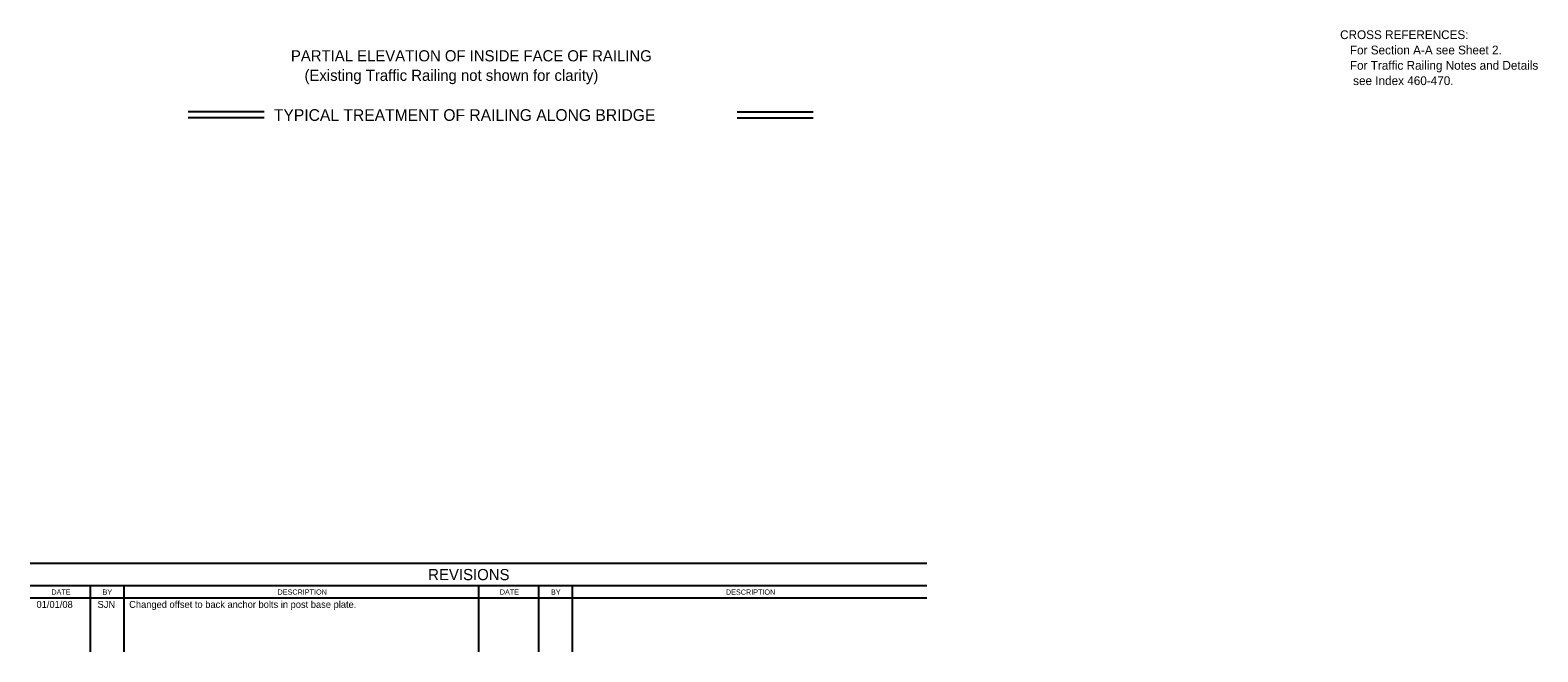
# Model space of a CAD drawing. Extents: x 21516.9 to 21589, y 56154.7 to 56194.3.
# Drawn here: x 21516.88 to 21551.53, y 56154.67 to 56168.95 of the extents above; entities that cross this region are included whole.
import ezdxf

# ---------------------------------------------------------------- set-up
doc = ezdxf.new("R2010")
doc.units = 0
for name, color, linetype in [('PlotBorder_dp', 7, 'Continuous'), ('SheetBorder_dp', 7, 'Continuous'), ('SheetLines_dp', 7, 'Continuous')]:
    doc.layers.add(name, color=color, linetype=linetype)

msp = doc.modelspace()

# ---------------------------------------------------------------- linework, layer by layer
at = {"layer": 'PlotBorder_dp'}
for p, q in [((21522.256, 56167.072), (21520.508, 56167.072)), ((21522.256, 56166.93), (21520.508, 56166.93)), ((21533.125, 56167.072), (21534.874, 56167.072)), ((21533.125, 56166.93), (21534.874, 56166.93))]:
    msp.add_line(p, q, dxfattribs=at)
at = {"layer": 'SheetLines_dp'}
for p, q in [((21537.488, 56156.697), (21516.877, 56156.697)), ((21537.488, 56156.182), (21516.877, 56156.182)), ((21518.253, 56156.182), (21518.253, 56154.667)), ((21519.027, 56156.182), (21519.027, 56154.667)), ((21527.183, 56156.182), (21527.183, 56154.667)), ((21528.559, 56156.182), (21528.559, 56154.667)), ((21529.333, 56156.182), (21529.333, 56154.667)), ((21516.877, 56155.909), (21537.488, 56155.909))]:
    msp.add_line(p, q, dxfattribs=at)

# ---------------------------------------------------------------- texts
at = {"layer": 'PlotBorder_dp'}
for s, height, p in [('CROSS REFERENCES:', 0.2016, (21546.984, 56168.741)), ('   For Section A-A see Sheet 2.', 0.2016, (21546.984, 56168.389)), ('PARTIAL ELEVATION OF INSIDE FACE OF RAILING', 0.256, (21522.87, 56168.229)), ('   For Traffic Railing Notes and Details ', 0.2016, (21546.984, 56168.037)), ('(Existing Traffic Railing not shown for clarity)', 0.256, (21523.182, 56167.781)), ('    see Index 460-470.', 0.2016, (21546.984, 56167.685))]:
    msp.add_text(s, height=height, dxfattribs=at).set_placement(p)
at = {"layer": 'SheetBorder_dp'}
for s, height, p in [('TYPICAL TREATMENT OF RAILING ALONG BRIDGE', 0.2688, (21522.478, 56166.862)), ('REVISIONS', 0.2567, (21526.025, 56156.313)), ('BY', 0.1201, (21518.541, 56155.979)), ('BY', 0.1201, (21528.847, 56155.979)), ('01/01/08', 0.16, (21517.023, 56155.676)), ('SJN', 0.16, (21518.426, 56155.676)), ('Changed offset to back anchor bolts in post base plate.', 0.16, (21519.152, 56155.676))]:
    msp.add_text(s, height=height, dxfattribs=at).set_placement(p)
for s, height, rotation, p in [('DATE', 0.1196, 359.8693, (21517.365, 56155.98)), ('DESCRIPTION', 0.12007, 0.0498, (21522.563, 56155.979)), ('DATE', 0.1196, 359.8693, (21527.671, 56155.98)), ('DESCRIPTION', 0.12007, 0.0498, (21532.869, 56155.979))]:
    msp.add_text(s, height=height, rotation=rotation, dxfattribs=at).set_placement(p)

doc.saveas('drawing.dxf')
